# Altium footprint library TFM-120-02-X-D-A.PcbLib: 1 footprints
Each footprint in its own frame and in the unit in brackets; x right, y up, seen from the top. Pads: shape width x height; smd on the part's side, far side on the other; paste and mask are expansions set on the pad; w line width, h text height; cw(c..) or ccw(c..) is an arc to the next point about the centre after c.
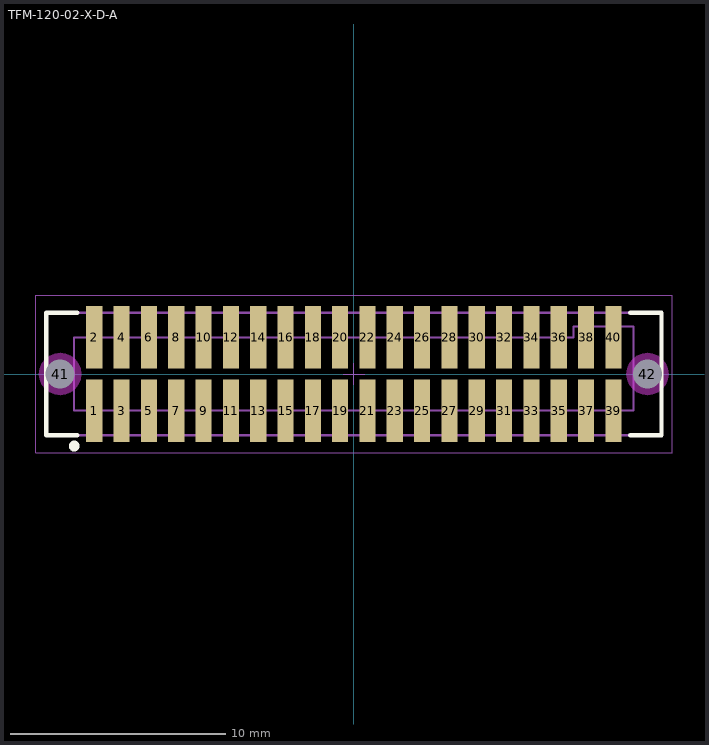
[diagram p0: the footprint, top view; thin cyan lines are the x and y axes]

## TFM-120-02-X-D-A [mm] "1.27mm pitch, 40 pin, terminal strip; w/alignment pins, SMT"
height 5.59
pads (42):
  rect 0.75x2.9 smd mask+0: 1(-12.065,-1.714) 2(-12.065,1.714) 3(-10.795,-1.714) 4(-10.795,1.714) 5(-9.525,-1.714) 6(-9.525,1.714) 7(-8.255,-1.714) 8(-8.255,1.714) 9(-6.985,-1.714) 10(-6.985,1.714) 11(-5.715,-1.714) 12(-5.715,1.714) 13(-4.445,-1.714) 14(-4.445,1.714) 15(-3.175,-1.714) 16(-3.175,1.714) 17(-1.905,-1.714) 18(-1.905,1.714) 19(-0.635,-1.714) 20(-0.635,1.714) 21(0.635,-1.714) 22(0.635,1.714) 23(1.905,-1.714) 24(1.905,1.714) 25(3.175,-1.714) 26(3.175,1.714) 27(4.445,-1.714) 28(4.445,1.714) 29(5.715,-1.714) 30(5.715,1.714) 31(6.985,-1.714) 32(6.985,1.714) 33(8.255,-1.714) 34(8.255,1.714) 35(9.525,-1.714) 36(9.525,1.714) 37(10.795,-1.714) 38(10.795,1.714) 39(12.065,-1.714) 40(12.065,1.714)
  round 1 hole 1.35 unplated mask+0: 41(-13.652,0) 42(13.652,0)
Top Overlay:
  circle w0.25: c-13,-3.35 r0.125
  lines w0.2: -12.85,-2.85 -14.3,-2.85 -14.3,2.85 -12.85,2.85 ; 12.85,-2.85 14.3,-2.85 14.3,2.85 12.85,2.85
Keep-Out Layer:
  pour cut-out: -12.669,0 -12.703,0.255 -12.801,0.492 -12.957,0.695 -13.161,0.852 -13.398,0.95 -13.653,0.983 -13.907,0.95 -14.144,0.852 -14.348,0.695 -14.504,0.492 -14.603,0.255 -14.636,0 -14.603,-0.255 -14.504,-0.492 -14.348,-0.695 -14.144,-0.852 -13.907,-0.95 -13.653,-0.983 -13.398,-0.95 -13.161,-0.852 -12.957,-0.695 -12.801,-0.492 -12.703,-0.255
  pour cut-out: 14.636,0 14.603,0.255 14.504,0.492 14.348,0.695 14.144,0.852 13.907,0.95 13.653,0.983 13.398,0.95 13.161,0.852 12.957,0.695 12.801,0.492 12.703,0.255 12.669,0 12.703,-0.255 12.801,-0.492 12.957,-0.695 13.161,-0.852 13.398,-0.95 13.653,-0.983 13.907,-0.95 14.144,-0.852 14.348,-0.695 14.504,-0.492 14.603,-0.255
Mechanical 12:
  lines w0.001: -14.3,-2.85 14.3,-2.85 14.3,2.85 -14.3,2.85 -14.3,-2.85 ; -13.005,-1.702 13.005,-1.702 13.005,2.21 10.211,2.21 10.211,1.702 -13.005,1.702 -13.005,-1.702
Mechanical 13:
  circle w0.1: c-12.989,-3.356 r0.127
  lines w0.1: -14.3,-2.85 14.3,-2.85 14.3,2.85 -14.3,2.85 -14.3,-2.85 ; -13.005,-1.702 13.005,-1.702 13.005,2.21 10.211,2.21 10.211,1.702 -13.005,1.702 -13.005,-1.702
  text ".Designator" at 0,-0.127 h1.52
Mechanical 15:
  lines w0.05: -0.5,0 0.5,0 ; 0,-0.5 0,0.5 ; -14.783,-3.65 14.8,-3.65 14.8,3.65 -14.783,3.65 -14.783,-3.65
